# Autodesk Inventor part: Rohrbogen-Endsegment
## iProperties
Created: 2006-10
Part Number: Rohrbogen-Endsegment
Cost Center: 3,48 kg
Material: 1.4301 (X5CrNi18 10)
Document SubType Name: Sheet Metal
Designer: grote
Authority: 435012,9 mm^3
Manufacturer: Standard
Standards Organization: Custom
Objekthöhe: 10,000 mm
SaveDate: 2006-10-11
SaveTime: 08:22
FileName: Rohrbogen-Endsegment
TotalMass: 3,48 kg
TotalVolume: 435012,9 mm^3
SM_Thickness: 10 mm
SM_Style: NIRO-V80(t =4-10 mm)
SM_Extents: 497,220 mm x 94,852 mm
SM_Square: 47162 mm²
SM_Extents_Width: 497,220 mm
SM_Extents_Length: 94,852 mm
Author: grote
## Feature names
1. Trennen3
2. Abgeleiteter Körper1 [Tagging]
3. ExtrusionAbwicklung1
